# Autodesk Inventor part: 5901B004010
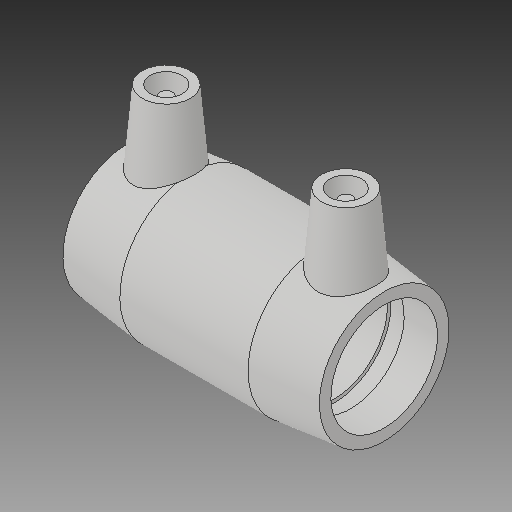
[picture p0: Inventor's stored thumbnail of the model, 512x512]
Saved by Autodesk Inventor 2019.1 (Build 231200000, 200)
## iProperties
Created: 2017-06
Part Number: 5901B004010
Material: Generic
Description: PLASSON IPS COUPLER 1''
Document SubType Name: Modeling
Designer: KIM
Mass: 8622.19 g
Surface Area: 6772.47 cm^2
Volume: 8622.19 cm^3
Density: 1 g/cm^3
Appearance: Default
Author: KIM
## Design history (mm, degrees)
derived "5901B.ipt"
feature "Solid1::5901B.ipt"
tag "TaggingFeature1"
body "Solid1"
other parameters: "d0" = 80.01, "d1" = 33.3, "d2" = 44.958, "d3" = 39.116, "d4" = 20.0025, "d5" = 40.4622, "d6" = 26.64, "d7" = 33.3, "d8" = 168 deg, "d10" = 15.6464, "d11" = 5.21547, "d13" = 80.01, "d14" = 17.6296, "d18" = 33.3, "d19" = 3.52592, "d20" = 168 deg, "d22" = 42.26052, "d23" = 44.958, "d24" = 40.9927, "d25" = 135 deg, "d26" = 36.0045, "d27" = 135 deg, "d29" = 42.164, "d30" = 15, "d31" = 28.0035, "d34" = 5 deg, "d35" = 15, "d39" = 5 deg, "d41" = 4, "d42" = 14, "d43" = 0, "d45" = 4, "d46" = 14, "d47" = 0, "d48" = 3, "d49" = 0, "d50" = 3, "d51" = 0, "d52" = 11.34364, "d53" = 2.83591, "d55" = 39.116, "d_" = 33.3, "L_" = 80.01, "L_1" = 39.116, "D_" = 44.958, "A_" = 42.164, "d_2" = 12, "B_" = 42.164
